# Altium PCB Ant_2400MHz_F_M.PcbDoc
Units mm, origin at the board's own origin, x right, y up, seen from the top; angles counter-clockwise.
Board outline 21.7 x 33.3 mm, 2 copper layers (Top Layer, Bottom Layer), stack 1.633 mm thick; 3 components, 3 nets, 5 pads, 32 vias.
Unrouted connection lines stored in the file: 1.
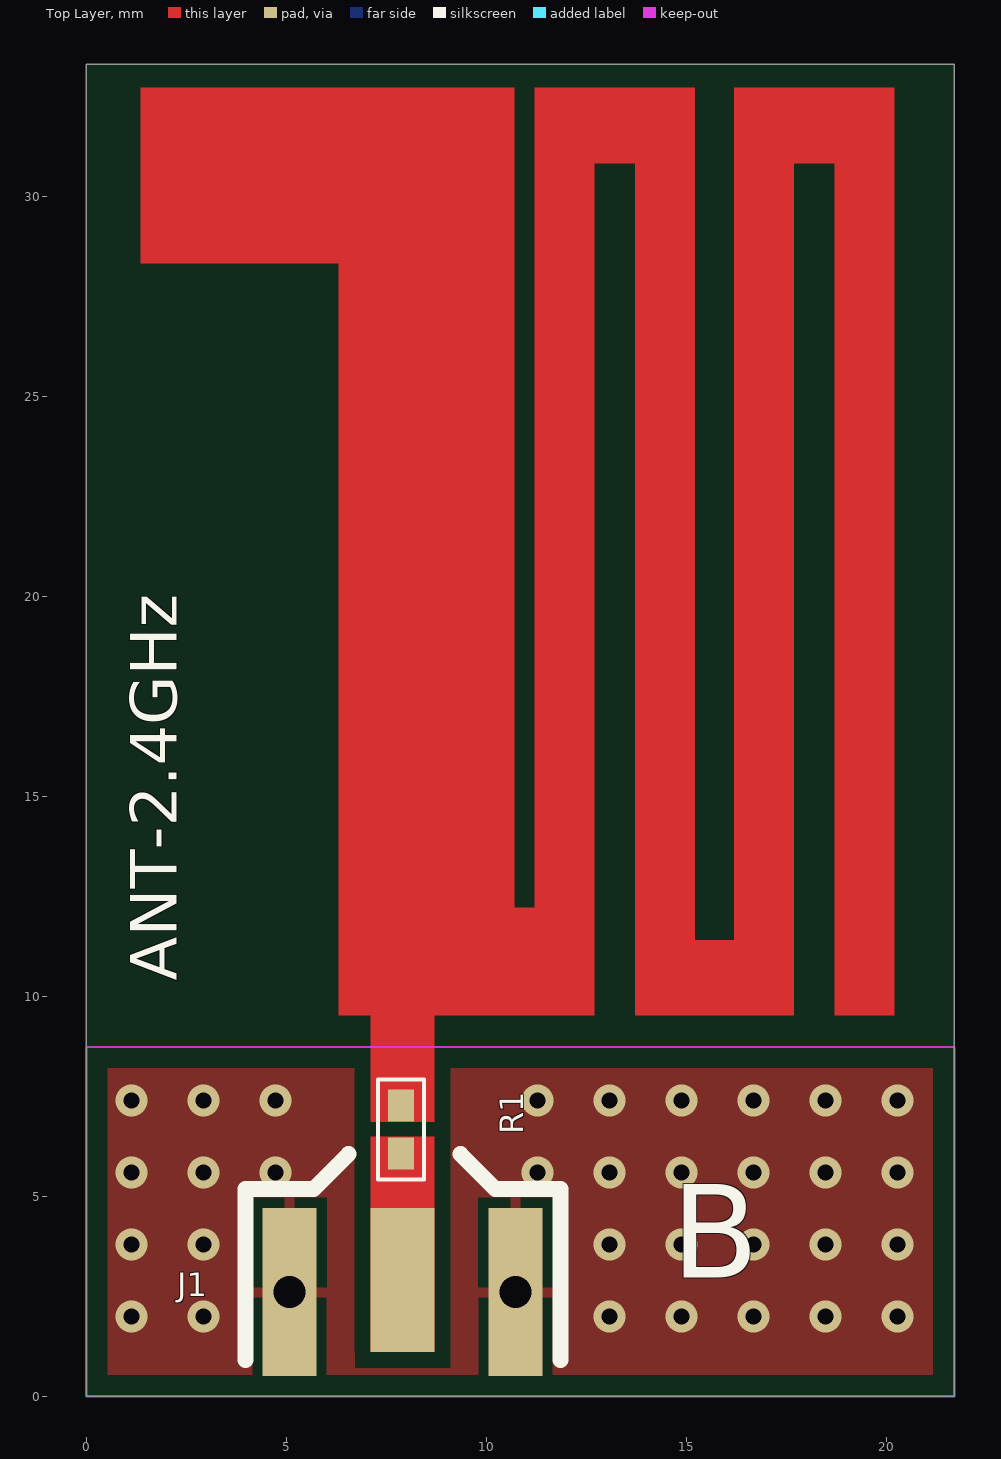
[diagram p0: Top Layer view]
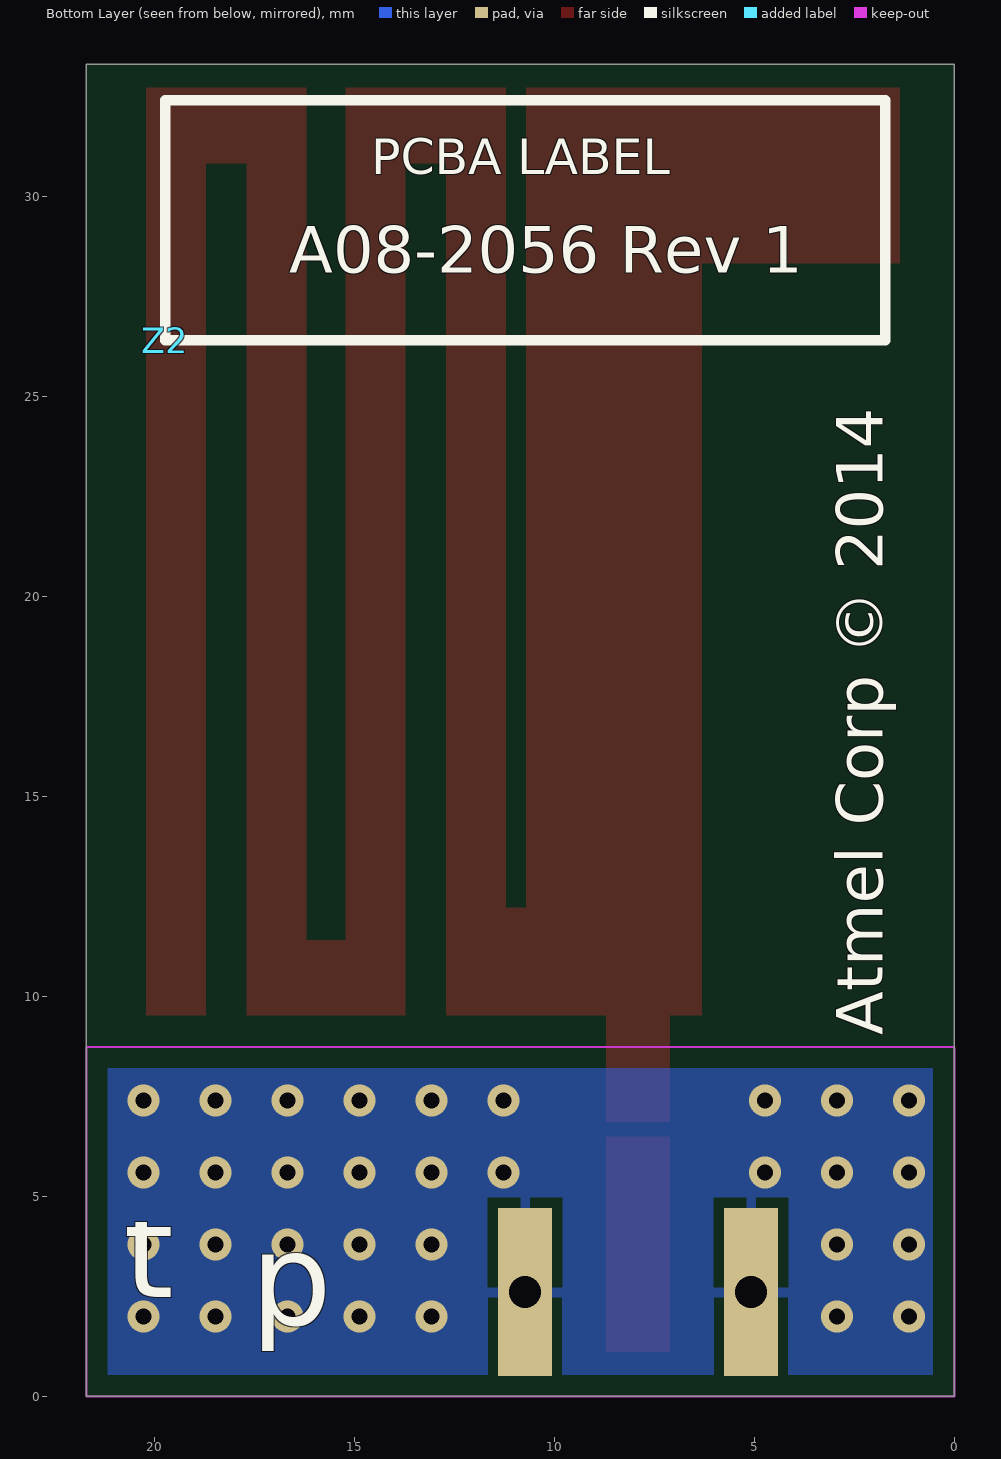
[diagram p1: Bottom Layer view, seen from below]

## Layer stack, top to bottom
Top Solder: solder mask 0.0102, Solder Resist, Dk 3.5
Top Layer: signal copper 0.0356
Dielectric1: core 1.562, FR-4, Dk 4.8
Bottom Layer: signal copper 0.0356
Bottom Solder: solder mask 0.0102, Solder Resist, Dk 3.5

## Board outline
0,0 0,33.3 21.7,33.3 21.7,0

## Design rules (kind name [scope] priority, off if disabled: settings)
AssemblyTestPointUsage [All] p1 off:
AssemblyTestpoint [All] p1 off: testpointundercomponent=TRUE minsize=1.016 maxsize=2.54 preferedsize=1.524 minholesize=0 maxholesize=1.016 preferedholesize=0.813 testpointgrid=0.025 usegrid=TRUE gridtolerance=0 allowsidetop=TRUE allowsidebottom=TRUE
Clearance Clearance_keepout [OnLayer('Keep-Out Layer')] p1: gap=0.5
Clearance Clearance_stripline [All vs (InNet('ANT') or InNet('NetJ1_1'))] p2: gap=0.4
ComponentClearance [All] p1 off: gap=0.254 collisioncheckmode=3 verticalgap=0.254 showdistances=FALSE
DiffPairsRouting [All] p1 off: maxlimit=0.254 minlimit=0.254 mostfreqgap=0.254 toplayer_minwidth=0.381 toplayer_maxwidth=0.381 toplayer_prefwidth=0.381 bottomlayer_minwidth=0.381 bottomlayer_maxwidth=0.381 bottomlayer_prefwidth=0.381 maxuncoupledlength=12.7
FabricationTestPointUsage [All] p1 off: valid=0 allowmultiple=FALSE
FabricationTestpoint [All] p1 off: side=3 testpointundercomponent=TRUE minsize=1.016 maxsize=2.54 preferedsize=1.524 minholesize=0 maxholesize=1.016 preferedholesize=0.813 testpointgrid=0.025 allowsidetop=TRUE allowsidebottom=TRUE usegrid=TRUE gridtolerance=0
FanoutControl Fanout_BGA [IsBGA] p1 off: bgadir=Out bgaviamode=Centered fanoutstyle=Auto fanoutdirection=Alternating viagrid=0.025 // Fanout_BGA (Default Rule)
FanoutControl Fanout_LCC [IsLCC] p2 off: bgadir=Out bgaviamode=Centered fanoutstyle=Auto fanoutdirection=Alternating viagrid=0.025 // Fanout_LCC (Default Rule)
FanoutControl Fanout_SOIC [IsSOIC] p3 off: bgadir=Out bgaviamode=Centered fanoutstyle=Auto fanoutdirection=Alternating viagrid=0.025 // Fanout_SOIC (Default Rule)
FanoutControl Fanout_Small [(CompPinCount < 5)] p4 off: bgadir=Out bgaviamode=Centered fanoutstyle=Auto fanoutdirection=OutThenIn viagrid=0.025 // Fanout_Small (Default Rule)
FanoutControl Fanout_Default [All] p5 off: bgadir=Out bgaviamode=Centered fanoutstyle=Auto fanoutdirection=Alternating viagrid=0.025 // Fanout_Default (Default Rule)
PlaneClearance [All] p1 off: clearance=0.4
PlaneConnect PlaneConnect_via [IsVia] p1 off: planeconnectstyle=Direct reliefexpansion=0.508 reliefentries=4 reliefconductorwidth=0.254 reliefairgap=0.254
PlaneConnect [All] p2 off: planeconnectstyle=Relief reliefexpansion=0.508 reliefentries=4 reliefconductorwidth=0.254 reliefairgap=0.254
PolygonConnect PolygonConnect_via [IsVia] p1: connectstyle=Direct reliefconductorwidth=0.254 reliefentries=4 polygonreliefangle="90 Angle" airgapwidth=0.254
PolygonConnect [All] p2: connectstyle=Relief reliefconductorwidth=0.254 reliefentries=4 polygonreliefangle="90 Angle" airgapwidth=0.254
RoutingVias [All] p1: holewidth=0.4 width=0.8 viastyle="Through Hole" minholewidth=0.3 minwidth=0.6 maxholewidth=0.5 maxwidth=1
SilkToSolderMaskClearance SilkscreenOverComponentPads [IsPad] p1: minsilkscreentomaskgap=0.2 clearancetoexposedcopper=TRUE
SolderMaskExpansion [All] p1: expansion=0.102
Width [All] p1: maxlimit=0.254 minlimit=0.254 preferedwidth=0.254
15 further rules are at their usual default settings.

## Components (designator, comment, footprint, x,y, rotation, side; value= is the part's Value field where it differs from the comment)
J1 "SMA connetor" AP8-00443 7.905,2.905 r90 top locked
R1 "Comment" AP2-00000 7.865,6.666 r90 top
Z2 "PCBA_LABEL" AP8-00317 19.725,26.4 r180 bottom

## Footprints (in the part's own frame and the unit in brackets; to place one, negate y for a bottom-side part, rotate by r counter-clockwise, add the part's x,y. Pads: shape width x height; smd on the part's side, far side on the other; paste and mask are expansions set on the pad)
AP2-00000 [mm] "Standard 0402 SMD resistor footprint"
  rect 0.8x0.65 smd: 1(-0.6,0) 2(0.6,0)
  silkscreen extent -1.25,-0.58 1.25,0.58, body extent -0.5,-0.3 0.5,0.3, height 0.2
AP8-00317 [mm] "Placement area for 18x6mm sticker"
  silkscreen extent 0,0 18,6
AP8-00443 [mm] "SMA card edge mount 1.6mm substrate"
  rect 3.6x1.6 smd: 1(0,0)
  rect 4.2x1.35 hole 0.8 paste-0.3 mask+0: 2(-0.3,-2.825) 2.1(-0.3,2.825)
  silkscreen extent -2,-3.95 3.15,3.92, body extent -12.17,-3.18 1.16,3.18, height 3.71

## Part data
J1: library part A08-1047, "End Launch Jack Receptacle, Round Contact (de21535)"
R1: library part A02-0163, "RES 0.0 OHM 1/16W 0402 SMD"
Z2: library part A09-0611, "PCBA identification label PP Top White Gloss"

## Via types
v1: diameter 0.8, hole 0.4, Top Layer to Bottom Layer, tented both sides, 32 vias

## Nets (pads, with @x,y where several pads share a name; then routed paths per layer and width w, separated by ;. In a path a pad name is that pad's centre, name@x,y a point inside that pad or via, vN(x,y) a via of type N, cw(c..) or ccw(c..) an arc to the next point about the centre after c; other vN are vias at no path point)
Ant: R1.2
gnd: J1.2 J1.2.1
  other v1: 1.134,2 2.934,2 13.075,2 14.875,2 16.675,2 18.475,2 20.275,2 1.134,3.8 2.934,3.8 13.075,3.8 14.875,3.8 16.675,3.8 18.475,3.8 20.275,3.8 1.134,5.6 2.934,5.6 4.734,5.6 11.275,5.6 13.075,5.6 14.875,5.6 16.675,5.6 18.475,5.6 20.275,5.6 1.134,7.4 2.934,7.4 4.734,7.4 11.275,7.4 13.075,7.4 14.875,7.4 16.675,7.4 18.475,7.4 20.275,7.4
NetJ1_1: J1.1 R1.1

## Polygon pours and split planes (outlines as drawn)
gnd on Top Layer "GND-No Net" (solid): 0,8.6 0,0 21.7,0 21.7,8.6 0,8.6
gnd on Bottom Layer "GND-No Net" (solid, pour order 3): 0,8.7 0,0 21.7,0 21.7,8.7

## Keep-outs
Keep-Out Layer:
  lines w0.05: 0,8.7 0,0 21.7,0 21.7,8.7 ; 0,8.734 21.7,8.734

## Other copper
Top Layer:
  rectangle net NetJ1_1: 7.105,1.111 8.705,6.496
  rectangle net Ant: 6.305,9.516 10.705,32.715
  rectangle net Ant: 11.205,9.516 12.705,32.715
  rectangle net Ant: 10.705,9.516 11.236,12.216
  rectangle net Ant: 7.105,6.856 8.705,9.566
  rectangle net Ant: 12.705,30.826 13.715,32.715
  rectangle net Ant: 13.715,9.516 15.215,32.715
  rectangle net Ant: 15.215,9.516 16.225,11.405
  rectangle net Ant: 18.704,9.516 20.204,32.715
  rectangle net Ant: 17.694,30.826 18.704,32.715
  rectangle net Ant: 16.194,9.516 17.694,32.715
  region net Ant: 6.305,28.32 6.305,32.715 1.36,32.715 1.36,28.32
  pour cut-out: 6.697,6.856 6.697,6.496 9.113,6.496 9.113,6.856

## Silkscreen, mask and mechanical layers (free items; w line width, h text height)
Top Overlay:
  text "ANT-2.4GHz" at 2.645,10.39 h2 r90
  text "B" at 14.625,2.2 h4
Bottom Overlay:
  text "A08-2056 Rev 1" at 16.625,27.7 h2
  text "Atmel Corp © 2014" at 1.405,9.02 h2 r270
  text "t" at 20.768,1.721 h4
  text "p" at 17.595,1.02 h4
Top Paste:
  rectangle: 4.505,0.756 5.655,4.606
  rectangle: 10.155,0.756 11.305,4.606
Bottom Paste:
  rectangle: 10.155,0.756 11.305,4.606
  rectangle: 4.505,0.756 5.655,4.606
Top Solder:
  rectangle: 5.805,5.136 6.71,8.226
  rectangle: 9.101,5.116 9.995,8.206
  rectangle: 7.105,7.956 8.705,9.606
  rectangle: 7.105,5.006 8.705,5.406
Mechanical 1:
  the board outline again, w0.2
Mechanical 4:
  drawing of 171 lines, arcs and shapes, not listed
  text "Layer stackup" at -111.775,83.95 h5
  text "SOLDER LEVEL" at -89.755,73.772 h1.78
  text "( SEE NOTE 2A )" at -66.768,73.772 h1.78
  text "COPPER PLATE" at -89.755,71.232 h1.78
  text "35 um" at -64.482,69.962 h1.78
  text "LAYER 1" at -123.029,68.692 h1.78
  text "COPPER FOIL" at -89.755,68.692 h1.78
  text "}" at -68.038,68.565 h4.44
  text "Note 3" at -138.225,49.45 h1.52
  text "( SEE NOTE 1A )" at -57.385,48.3 h1.78
  text "CORE" at -89.055,48.261 h1.78
  text "1526 um" at -74.704,48.261 h1.78
  text "Prepregs" at -89.541,30.918 h1.78
  text "LAYER 2" at -120.325,27.18 h1.78
  text "COPPER FOIL" at -89.755,26.782 h1.78
  text "35 um" at -64.482,25.512 h1.78
  text "COPPER PLATE" at -89.755,24.242 h1.78
  text "}" at -68.038,24.115 h4.44
  text "SOLDER LEVEL" at -89.755,21.702 h1.78
  text "( SEE NOTE 2A )" at -66.768,21.702 h1.78
  text "NOTE  1A:  FR4" at -116.758,14.161 h1.78
  text "2A:  SURFACE PROTECTION: Chemical Gold" at -107.854,10.459 h1.78
  text "3:  PCB Thickness to be calculated based on Stack up" at -106.4,7.405 h1.52
  text "THE BOARD MUST BE RoHS COMPLIANT" at -107.999,4.497 h1.78
  text "DETAIL A ( CROSS-SECTION )" at -116.261,-0.749 h3.05
  text "SCALE = NONE" at -97.084,-5.321 h1.78
Mechanical 16:
  lines w0.127: -202.966,-41.702 -197.886,-41.702 ; -202.966,28.958 -197.886,28.958 ; -202.966,99.443 -197.886,99.443 ; -153.69,-112.187 -153.69,-107.107 ; -153.69,164.673 -153.69,169.753 ; -109.666,164.673 -109.666,169.753 ; -104.541,-112.187 -104.541,-107.107 ; -60.491,164.673 -60.491,169.753 ; -55.392,-112.187 -55.392,-107.107 ; -6.116,-112.187 -6.116,-107.107 ; -6.116,164.673 -6.116,169.753 ; 43.033,-112.187 43.033,-107.107 ; 43.033,164.673 43.033,169.753 ; 71.354,-99.487 185.654,-99.487 ; 71.354,-91.867 185.654,-91.867 ; 71.354,-84.247 109.454,-84.247 ; 92.182,-112.187 92.182,-107.107 ; 92.182,164.673 92.182,169.753 ; 109.454,-107.107 109.454,-91.867 109.454,-76.627 ; 141.458,-112.187 141.458,-107.107 ; 141.458,164.673 141.458,169.753 ; 162.794,-107.107 162.794,-91.867 ; 185.654,-41.702 190.734,-41.702 ; 185.654,28.913 190.734,28.913 ; 185.654,99.398 190.734,99.398 ; 71.354,-107.107 71.354,-76.627 ; 71.354,-107.107 185.654,-107.107 ; 71.354,-107.107 35.794,-107.107 35.794,-76.627 71.354,-76.627 ; 71.354,-76.627 109.454,-76.627 ; 109.454,-76.627 185.654,-76.627 185.654,-107.107 ; 185.654,-107.107 185.654,164.673 -197.886,164.673 -197.886,-107.107 185.654,-107.107 ; -202.966,-112.187 190.734,-112.187 190.734,169.753 -202.966,169.753 -202.966,-112.187
  text "1" at -178.929,166.324 h0.67
  text "4" at -31.339,166.324 h0.67
  text "5" at 17.937,166.324 h0.67
  text "6" at 66.959,166.324 h0.67
  text "7" at 116.489,166.324 h0.67
  text "8" at 165.511,166.324 h0.67
  text "2" at -132.44,166.188 h0.67
  text "3" at -85.89,166.038 h0.67
  text "A" at -201.061,132.514 h0.67
  text "A" at 187.559,132.469 h0.67
  text "B" at 187.639,64.414 h0.67
  text "B" at -201.061,61.902 h0.67
  text "C" at -201.154,-6.275 h0.67
  text "C" at 188.009,-11.887 h0.67
  text "D" at -201.061,-78.989 h0.67
  text "D" at 187.559,-78.989 h0.67
  text "ENGINEER:" at 72.624,-79.167 h0.67
  text "TITLE:" at 110.724,-79.167 h0.67
  text "PCB DESIGNER:" at 72.624,-86.66 h0.67
  text "B" at 36.784,-91.787 h22
  text "DATE:" at 72.624,-94.407 h0.67
  text "PART NO.:" at 110.724,-94.407 h0.67
  text "REV:" at 164.064,-94.407 h0.67
  text ".PRINT_DATE" at 72.734,-98.287 h0.67
  text "ATMEL NORWAY" at 40.034,-99.187 h0.67
  text "Vestre Rosten 79" at 40.004,-101.265 h0.67
  text "FILE NAME:" at 72.624,-102.027 h0.67
  text "DWG NO:" at 110.724,-102.027 h0.67
  text "SCALE:" at 164.064,-102.027 h0.67
  text "N-7075 Tiller" at 40.004,-104.567 h0.67
  text ".PCB_FILE_NAME_NO_PATH" at 73.894,-105.075 h0.67
  text "2" at -129.306,-110.475 h0.67
  text "3" at -79.776,-110.475 h0.67
  text "4" at -30.754,-110.475 h0.67
  text "5" at 17.937,-110.475 h0.67
  text "6" at 66.959,-110.475 h0.67
  text "7" at 116.489,-110.475 h0.67
  text "8" at 165.511,-110.475 h0.67

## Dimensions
0,33.3 to 21.7,33.3 on Mechanical 4
21.7,33.3 to 21.7,0 on Mechanical 4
